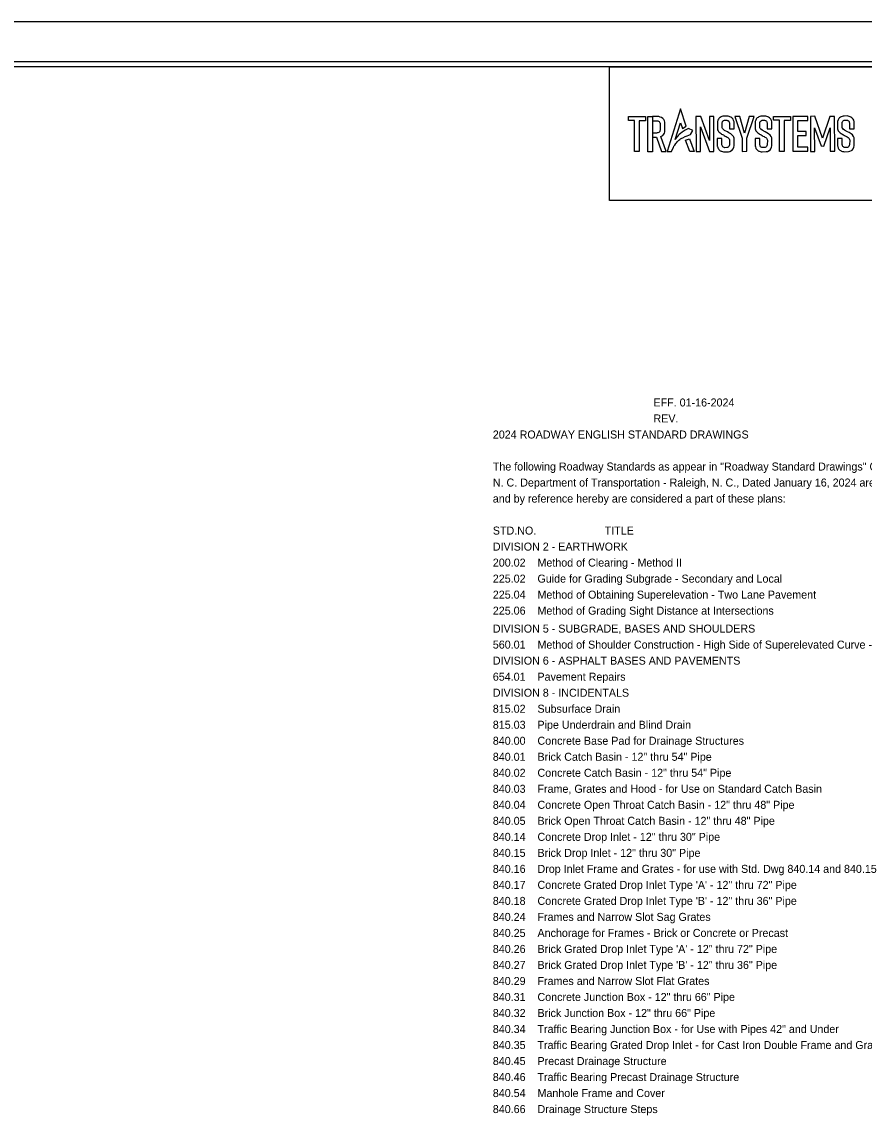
# Model space of a CAD drawing. Extents: x 1537922 to 1539606, y 409903 to 410998.
# Drawn here: x 1538895 to 1539316, y 410451 to 410998 of the extents above; entities that cross this region are included whole.
import ezdxf

# ---------------------------------------------------------------- set-up
doc = ezdxf.new("R2010")
doc.units = 0
for name, color, linetype in [('Old_Level_1', 7, 'Continuous'), ('Old_Level_58', 7, 'Continuous'), ('Sheet Cutting Line CELL', 7, 'Continuous'), ('Sheet Plan CELL', 7, 'Continuous'), ('Sheet Plot Border Inside CELL', 7, 'Continuous'), ('Sheet Plot Border Outside CELL', 7, 'Continuous')]:
    doc.layers.add(name, color=color, linetype=linetype)

msp = doc.modelspace()

# ---------------------------------------------------------------- linework, layer by layer
at = {"layer": 'Old_Level_1'}
for points in [[(1539224.12, 410954.94), (1539217.45, 410933.6), (1539219.67, 410933.61), (1539220.02, 410934.45), (1539220.59, 410935.61), (1539220.9, 410936.24), (1539221.28, 410936.78), (1539221.8, 410937.54), (1539222.13, 410938.01), (1539222.51, 410938.4), (1539222.89, 410938.79), (1539223.37, 410939.29), (1539223.78, 410939.56), (1539224.2, 410939.89), (1539224.76, 410940.21), (1539225.25, 410940.49), (1539226.47, 410941.06), (1539227.47, 410941.47), (1539229.11, 410942.03), (1539230.24, 410944.17), (1539228.07, 410945.13), (1539226.44, 410944.24), (1539225.06, 410943.34), (1539224.08, 410942.54), (1539223.55, 410942.11), (1539223.02, 410941.55), (1539222.49, 410940.98), (1539222.09, 410940.56), (1539221.71, 410939.91), (1539221.5, 410939.55), (1539224.13, 410947.93), (1539225.13, 410945.04), (1539227.03, 410946.29)], [(1539198.15, 410951.09), (1539206.62, 410951.1), (1539206.62, 410949.02), (1539203.51, 410949.02), (1539203.53, 410933.6), (1539201.18, 410933.6), (1539201.16, 410949.12), (1539198.19, 410949.12)], [(1539207.77, 410951.08), (1539210.09, 410951.09), (1539210.11, 410933.52), (1539207.79, 410933.52)], [(1539210.09, 410949), (1539212.48, 410949), (1539212.78, 410948.95), (1539213.18, 410948.79), (1539213.51, 410948.57), (1539213.74, 410948.3), (1539213.89, 410947.97), (1539214.02, 410947.71), (1539214.02, 410947.13), (1539214.03, 410944.64), (1539213.97, 410944.31), (1539213.88, 410943.87), (1539213.75, 410943.57), (1539213.55, 410943.31), (1539213.28, 410943.1), (1539212.86, 410942.95), (1539212.53, 410942.9), (1539212.2, 410942.86), (1539210.1, 410942.85), (1539210.11, 410940.74), (1539212.22, 410940.76), (1539214.59, 410933.59), (1539217, 410933.62), (1539214.35, 410941.16), (1539214.73, 410941.29), (1539215.27, 410941.69), (1539215.75, 410942.22), (1539216.1, 410942.86), (1539216.32, 410943.49), (1539216.3, 410943.68), (1539216.34, 410948.24), (1539216.14, 410948.99), (1539215.78, 410949.67), (1539215.37, 410950.14), (1539214.67, 410950.61), (1539213.99, 410950.84), (1539213.31, 410951.06), (1539212.91, 410951.06), (1539210.09, 410951.09)], [(1539231.89, 410951.12), (1539231.9, 410933.66), (1539234.14, 410933.66), (1539234.13, 410945.94), (1539238.58, 410933.64), (1539240.83, 410933.67), (1539240.81, 410951.17), (1539238.63, 410951.17), (1539238.65, 410939.19), (1539234.24, 410951.13)], [(1539248.58, 410944.95), (1539250.9, 410944.95), (1539250.89, 410948.43), (1539250.7, 410949.13), (1539250.42, 410949.72), (1539250.12, 410950.11), (1539249.75, 410950.46), (1539249.31, 410950.75), (1539248.88, 410950.92), (1539248.88, 410950.92), (1539248.42, 410951.12), (1539247.94, 410951.24), (1539247.62, 410951.32), (1539245.87, 410951.28), (1539245.34, 410951.19), (1539244.88, 410951.11), (1539244.42, 410950.87), (1539244.02, 410950.66), (1539243.62, 410950.38), (1539243.32, 410950.06), (1539243.07, 410949.7), (1539242.88, 410949.3), (1539242.62, 410948.61), (1539242.57, 410948.09), (1539242.57, 410944.92), (1539242.69, 410944.45), (1539242.92, 410943.95), (1539243.21, 410943.54), (1539243.5, 410943.23), (1539243.95, 410942.88), (1539244.41, 410942.54), (1539244.69, 410942.32), (1539245.17, 410942.09), (1539245.66, 410941.87), (1539246.05, 410941.61), (1539246.49, 410941.33), (1539247.02, 410941.06), (1539247.45, 410940.84), (1539247.88, 410940.53), (1539248.19, 410940.23), (1539248.44, 410939.99), (1539248.59, 410939.51), (1539248.69, 410939.21), (1539248.65, 410936.98), (1539248.49, 410936.49), (1539248.24, 410936.07), (1539247.92, 410935.78), (1539247.56, 410935.62), (1539247.22, 410935.55), (1539246.26, 410935.53), (1539245.94, 410935.62), (1539245.61, 410935.81), (1539245.28, 410936.01), (1539245.14, 410936.34), (1539244.99, 410936.68), (1539244.88, 410936.94), (1539244.84, 410940.06), (1539242.51, 410940.03), (1539242.55, 410936.32), (1539242.67, 410936.04), (1539242.94, 410935.17), (1539243.11, 410934.88), (1539243.37, 410934.56), (1539243.75, 410934.19), (1539244.05, 410934), (1539244.49, 410933.81), (1539244.64, 410933.75), (1539245.07, 410933.56), (1539245.61, 410933.51), (1539246, 410933.47), (1539248.14, 410933.53), (1539248.74, 410933.67), (1539249.56, 410934.04), (1539249.84, 410934.17), (1539250.46, 410934.96), (1539250.8, 410935.75), (1539250.95, 410936.46), (1539250.9, 410939.88), (1539250.89, 410940.35), (1539250.76, 410940.73), (1539250.57, 410941.08), (1539250.03, 410941.84), (1539249.32, 410942.4), (1539248.35, 410942.98), (1539247.6, 410943.42), (1539246.14, 410944.19), (1539245.39, 410944.75), (1539245.06, 410945.17), (1539244.98, 410945.45), (1539244.9, 410945.74), (1539244.95, 410948.17), (1539245.07, 410948.42), (1539245.2, 410948.68), (1539245.37, 410948.83), (1539245.61, 410949.03), (1539245.86, 410949.13), (1539246.12, 410949.24), (1539246.27, 410949.21), (1539246.29, 410949.29), (1539247.24, 410949.27), (1539247.52, 410949.16), (1539247.8, 410949.05), (1539248.08, 410948.94), (1539248.21, 410948.75), (1539248.39, 410948.47), (1539248.48, 410948.19), (1539248.58, 410947.92), (1539248.57, 410947.61)], [(1539253.86, 410951.13), (1539251.32, 410951.13), (1539254.94, 410940.25), (1539254.97, 410933.7), (1539257.36, 410933.71), (1539257.33, 410940.21), (1539260.98, 410951.17), (1539258.49, 410951.1), (1539256.18, 410942.76)], [(1539267.46, 410944.97), (1539269.77, 410944.97), (1539269.76, 410948.45), (1539269.57, 410949.15), (1539269.29, 410949.74), (1539268.99, 410950.13), (1539268.62, 410950.48), (1539268.18, 410950.77), (1539267.75, 410950.94), (1539267.75, 410950.94), (1539267.3, 410951.13), (1539266.81, 410951.25), (1539266.49, 410951.34), (1539264.74, 410951.3), (1539264.21, 410951.21), (1539263.76, 410951.13), (1539263.3, 410950.89), (1539262.89, 410950.68), (1539262.5, 410950.39), (1539262.19, 410950.08), (1539261.94, 410949.72), (1539261.75, 410949.32), (1539261.5, 410948.62), (1539261.44, 410948.11), (1539261.45, 410944.94), (1539261.56, 410944.46), (1539261.79, 410943.97), (1539262.08, 410943.56), (1539262.37, 410943.25), (1539262.83, 410942.9), (1539263.28, 410942.55), (1539263.56, 410942.33), (1539264.05, 410942.11), (1539264.53, 410941.88), (1539264.92, 410941.63), (1539265.36, 410941.34), (1539265.89, 410941.08), (1539266.32, 410940.86), (1539266.75, 410940.54), (1539267.06, 410940.25), (1539267.31, 410940.01), (1539267.46, 410939.53), (1539267.56, 410939.23), (1539267.52, 410936.99), (1539267.36, 410936.51), (1539267.12, 410936.09), (1539266.79, 410935.8), (1539266.43, 410935.64), (1539266.09, 410935.57), (1539265.13, 410935.55), (1539264.81, 410935.64), (1539264.48, 410935.83), (1539264.15, 410936.02), (1539264.01, 410936.36), (1539263.87, 410936.69), (1539263.75, 410936.96), (1539263.72, 410940.07), (1539261.38, 410940.05), (1539261.42, 410936.34), (1539261.54, 410936.05), (1539261.81, 410935.19), (1539261.99, 410934.9), (1539262.24, 410934.58), (1539262.62, 410934.21), (1539262.92, 410934.01), (1539263.36, 410933.83), (1539263.52, 410933.76), (1539263.95, 410933.58), (1539264.48, 410933.53), (1539264.87, 410933.49), (1539267.02, 410933.54), (1539267.61, 410933.69), (1539268.44, 410934.06), (1539268.71, 410934.19), (1539269.34, 410934.98), (1539269.67, 410935.76), (1539269.83, 410936.47), (1539269.77, 410939.9), (1539269.76, 410940.37), (1539269.63, 410940.74), (1539269.44, 410941.1), (1539268.9, 410941.86), (1539268.19, 410942.41), (1539267.22, 410942.99), (1539266.48, 410943.44), (1539265.01, 410944.2), (1539264.26, 410944.76), (1539263.93, 410945.19), (1539263.85, 410945.47), (1539263.77, 410945.75), (1539263.82, 410948.19), (1539263.94, 410948.44), (1539264.07, 410948.7), (1539264.25, 410948.85), (1539264.48, 410949.04), (1539264.74, 410949.15), (1539265, 410949.26), (1539265.14, 410949.23), (1539265.16, 410949.3), (1539266.12, 410949.29), (1539266.39, 410949.18), (1539266.67, 410949.07), (1539266.95, 410948.96), (1539267.08, 410948.77), (1539267.26, 410948.49), (1539267.36, 410948.21), (1539267.45, 410947.94), (1539267.44, 410947.63)], [(1539270.61, 410951.16), (1539279.08, 410951.16), (1539279.08, 410949.09), (1539275.97, 410949.09), (1539275.99, 410933.66), (1539273.64, 410933.66), (1539273.62, 410949.19), (1539270.65, 410949.19)], [(1539287.69, 410951.16), (1539280.3, 410951.15), (1539280.32, 410933.73), (1539287.79, 410933.74), (1539287.79, 410935.71), (1539282.74, 410935.7), (1539282.74, 410941.55), (1539286.95, 410941.55), (1539286.95, 410943.62), (1539282.7, 410943.62), (1539282.69, 410949.12), (1539287.71, 410949.12)], [(1539295.06, 410940.31), (1539291.25, 410951.23), (1539289.04, 410951.13), (1539289.12, 410933.67), (1539291.23, 410933.68), (1539291.17, 410945.36), (1539294.44, 410936.37), (1539295.79, 410936.34), (1539298.86, 410945.47), (1539298.9, 410933.75), (1539301.18, 410933.75), (1539301.12, 410951.18), (1539298.82, 410951.17)], [(1539308.59, 410945), (1539310.9, 410945.01), (1539310.9, 410948.48), (1539310.7, 410949.19), (1539310.42, 410949.78), (1539310.12, 410950.17), (1539309.75, 410950.52), (1539309.31, 410950.8), (1539308.89, 410950.98), (1539308.89, 410950.98), (1539308.43, 410951.17), (1539307.94, 410951.29), (1539307.62, 410951.37), (1539305.87, 410951.34), (1539305.35, 410951.25), (1539304.89, 410951.17), (1539304.43, 410950.93), (1539304.02, 410950.72), (1539303.63, 410950.43), (1539303.32, 410950.12), (1539303.08, 410949.75), (1539302.88, 410949.36), (1539302.63, 410948.66), (1539302.58, 410948.15), (1539302.58, 410944.98), (1539302.69, 410944.5), (1539302.92, 410944.01), (1539303.21, 410943.6), (1539303.51, 410943.29), (1539303.96, 410942.94), (1539304.41, 410942.59), (1539304.69, 410942.37), (1539305.18, 410942.15), (1539305.66, 410941.92), (1539306.05, 410941.67), (1539306.49, 410941.38), (1539307.02, 410941.12), (1539307.45, 410940.9), (1539307.88, 410940.58), (1539308.19, 410940.29), (1539308.44, 410940.05), (1539308.6, 410939.57), (1539308.69, 410939.27), (1539308.65, 410937.03), (1539308.49, 410936.55), (1539308.25, 410936.13), (1539307.92, 410935.84), (1539307.57, 410935.68), (1539307.22, 410935.6), (1539306.26, 410935.58), (1539305.94, 410935.67), (1539305.61, 410935.87), (1539305.28, 410936.06), (1539305.14, 410936.4), (1539305, 410936.73), (1539304.89, 410937), (1539304.85, 410940.11), (1539302.51, 410940.08), (1539302.55, 410936.37), (1539302.67, 410936.09), (1539302.94, 410935.23), (1539303.12, 410934.94), (1539303.37, 410934.62), (1539303.75, 410934.24), (1539304.05, 410934.05), (1539304.49, 410933.87), (1539304.65, 410933.8), (1539305.08, 410933.62), (1539305.61, 410933.57), (1539306.01, 410933.53), (1539308.15, 410933.58), (1539308.74, 410933.72), (1539309.57, 410934.1), (1539309.85, 410934.22), (1539310.47, 410935.01), (1539310.8, 410935.8), (1539310.96, 410936.51), (1539310.9, 410939.93), (1539310.9, 410940.41), (1539310.77, 410940.78), (1539310.57, 410941.14), (1539310.04, 410941.9), (1539309.33, 410942.45), (1539308.35, 410943.03), (1539307.61, 410943.48), (1539306.14, 410944.24), (1539305.39, 410944.8), (1539305.06, 410945.23), (1539304.98, 410945.51), (1539304.91, 410945.79), (1539304.95, 410948.22), (1539305.08, 410948.48), (1539305.2, 410948.73), (1539305.38, 410948.89), (1539305.61, 410949.08), (1539305.87, 410949.19), (1539306.13, 410949.3), (1539306.28, 410949.27), (1539306.29, 410949.34), (1539307.25, 410949.33), (1539307.53, 410949.22), (1539307.8, 410949.11), (1539308.08, 410949), (1539308.21, 410948.8), (1539308.4, 410948.53), (1539308.49, 410948.25), (1539308.58, 410947.97), (1539308.57, 410947.67)], [(1539226.73, 410939.23), (1539228.65, 410940), (1539230.91, 410933.56), (1539228.81, 410933.64)]]:
    msp.add_lwpolyline(points, close=True, dxfattribs=at)
at = {"layer": 'Old_Level_58'}
msp.add_lwpolyline([(1539188.77, 410975.85), (1539388.82, 410975.85), (1539388.82, 410909.16), (1539188.77, 410909.16)], close=True, dxfattribs=at)
at = {"layer": 'Sheet Cutting Line CELL'}
msp.add_line((1539605.87, 410998.35), (1537922.37, 410998.35), dxfattribs=at)
at = {"layer": 'Sheet Plan CELL'}
msp.add_lwpolyline([(1539588.87, 410975.85), (1538088.87, 410975.85), (1538088.87, 409925.85), (1539588.87, 409925.85)], close=True, dxfattribs=at)
at = {"layer": 'Sheet Plot Border Inside CELL'}
msp.add_lwpolyline([(1537935.37, 409923.35), (1539601.37, 409923.35), (1539601.37, 410978.35), (1537935.37, 410978.35)], close=True, dxfattribs=at)
at = {"layer": 'Sheet Plot Border Outside CELL'}
msp.add_lwpolyline([(1537922.37, 409903.35), (1539605.87, 409903.35), (1539605.87, 410998.35), (1537922.37, 410998.35)], close=True, dxfattribs=at)

# ---------------------------------------------------------------- texts
at = {"layer": 'Old_Level_1'}
for s, p in [('                                                      EFF. 01-16-2024', (1539130.41, 410806.24)), ('                                                      REV. ', (1539130.41, 410798.24)), ('2024 ROADWAY ENGLISH STANDARD DRAWINGS', (1539130.41, 410790.24)), ('The following Roadway Standards as appear in "Roadway Standard Drawings" Contracts Standards and Development Unit -', (1539130.41, 410774.24)), ('N. C. Department of Transportation - Raleigh, N. C., Dated January 16, 2024 are applicable to this project', (1539130.41, 410766.24)), ('and by reference hereby are considered a part of these plans:', (1539130.41, 410758.24)), ('STD.NO.                       TITLE', (1539130.41, 410742.24)), ('DIVISION 2 - EARTHWORK', (1539130.41, 410734.24)), ('200.02    Method of Clearing - Method II', (1539130.41, 410726.24)), ('225.02    Guide for Grading Subgrade - Secondary and Local', (1539130.41, 410718.24)), ('225.04    Method of Obtaining Superelevation - Two Lane Pavement', (1539130.41, 410710.24)), ('225.06    Method of Grading Sight Distance at Intersections', (1539130.41, 410702.24)), ('DIVISION 5 - SUBGRADE, BASES AND SHOULDERS', (1539130.41, 410693.27)), ('560.01    Method of Shoulder Construction - High Side of Superelevated Curve - Method I', (1539130.41, 410685.27)), ('DIVISION 6 - ASPHALT BASES AND PAVEMENTS', (1539130.41, 410677.27)), ('654.01    Pavement Repairs', (1539130.41, 410669.24)), ('DIVISION 8 - INCIDENTALS', (1539130.41, 410661.24)), ('815.02    Subsurface Drain', (1539130.41, 410653.24)), ('815.03    Pipe Underdrain and Blind Drain', (1539130.41, 410645.24)), ('840.00    Concrete Base Pad for Drainage Structures', (1539130.41, 410637.24)), ('840.01    Brick Catch Basin - 12" thru 54" Pipe', (1539130.41, 410629.24)), ('840.02    Concrete Catch Basin - 12" thru 54" Pipe', (1539130.41, 410621.24)), ('840.03    Frame, Grates and Hood - for Use on Standard Catch Basin', (1539130.41, 410613.24)), ('840.04    Concrete Open Throat Catch Basin - 12" thru 48" Pipe', (1539130.41, 410605.24)), ('840.05    Brick Open Throat Catch Basin - 12" thru 48" Pipe', (1539130.41, 410597.24)), ('840.14    Concrete Drop Inlet - 12" thru 30" Pipe', (1539130.41, 410589.24)), ('840.15    Brick Drop Inlet - 12" thru 30" Pipe', (1539130.41, 410581.24)), ('840.16    Drop Inlet Frame and Grates - for use with Std. Dwg 840.14 and 840.15', (1539130.41, 410573.24)), ('840.17    Concrete Grated Drop Inlet Type \'A\' - 12" thru 72" Pipe', (1539130.41, 410565.24)), ('840.18    Concrete Grated Drop Inlet Type \'B\' - 12" thru 36" Pipe', (1539130.41, 410557.24)), ('840.24    Frames and Narrow Slot Sag Grates', (1539130.41, 410549.24)), ('840.25    Anchorage for Frames - Brick or Concrete or Precast', (1539130.41, 410541.24)), ('840.26    Brick Grated Drop Inlet Type \'A\' - 12" thru 72" Pipe', (1539130.41, 410533.24)), ('840.27    Brick Grated Drop Inlet Type \'B\' - 12" thru 36" Pipe', (1539130.41, 410525.24)), ('840.29    Frames and Narrow Slot Flat Grates', (1539130.41, 410517.24)), ('840.31    Concrete Junction Box - 12" thru 66" Pipe', (1539130.41, 410509.24)), ('840.32    Brick Junction Box - 12" thru 66" Pipe', (1539130.41, 410501.24)), ('840.34    Traffic Bearing Junction Box - for Use with Pipes 42" and Under', (1539130.41, 410493.24)), ('840.35    Traffic Bearing Grated Drop Inlet - for Cast Iron Double Frame and Grates', (1539130.41, 410485.24)), ('840.45    Precast Drainage Structure', (1539130.41, 410477.24)), ('840.46    Traffic Bearing Precast Drainage Structure', (1539130.41, 410469.24)), ('840.54    Manhole Frame and Cover', (1539130.41, 410461.24)), ('840.66    Drainage Structure Steps', (1539130.41, 410453.24))]:
    msp.add_text(s, height=4, dxfattribs=at).set_placement(p)

doc.saveas('drawing.dxf')
